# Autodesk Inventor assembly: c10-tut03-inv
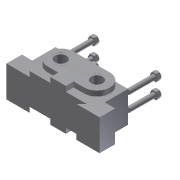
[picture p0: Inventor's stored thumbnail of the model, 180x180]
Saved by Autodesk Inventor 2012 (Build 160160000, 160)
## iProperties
Created: 2009-05
Part Number: c10-tut03-inv
Document SubType Name: Assembly
Designer: Sham
Author: Sham
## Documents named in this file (5)
- C:\Users\CadCim\Documents\SAILESH\inventor-2011-fact-prt\c10-inv-2011-prt\c10_inv_2012_prt\Tutorials\c10_tut03_inv\Double Bearing Assembly\c10-tut03-inv.iam
- C:\Users\CadCim\Documents\SAILESH\inventor-2011-fact-prt\c10-inv-2011-prt\c10_inv_2012_prt\Tutorials\c10_tut03_inv\Double Bearing Assembly\base.ipt
- C:\Users\CadCim\Documents\SAILESH\inventor-2011-fact-prt\c10-inv-2011-prt\c10_inv_2012_prt\Tutorials\c10_tut03_inv\Double Bearing Assembly\cap.ipt
- C:\Users\CadCim\Documents\SAILESH\inventor-2011-fact-prt\c10-inv-2011-prt\c10_inv_2012_prt\Tutorials\c10_tut03_inv\Double Bearing Assembly\bolt.ipt
- C:\Users\CadCim\Documents\SAILESH\inventor-2011-fact-prt\c10-inv-2011-prt\c10_inv_2012_prt\Tutorials\c10_tut03_inv\Double Bearing Assembly\bushing.ipt
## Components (10 placed, 4 different names)
1. base:1 — Mate:1, Mate:2, Mate:3, Insert:3, Insert:4
2. cap:1 — Mate:1, Mate:2, Mate:3, Insert:1, Insert:2
3. bushing:2 — Insert:3
4. bushing:3 — Insert:4
5. bolt:1 — Insert:1
6. bolt:6
7. bolt:7
8. bolt:8
9. bolt:5 — Insert:2
10. bolt:9
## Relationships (7: Insert 4, Mate 3)
- Mate:1: base:1 ↔ cap:1
- Mate:2: base:1 ↔ cap:1
- Mate:3: base:1 ↔ cap:1
- Insert:1: cap:1 ↔ bolt:1
- Insert:2: cap:1 ↔ bolt:5
- Insert:3: base:1 ↔ bushing:2
- Insert:4: base:1 ↔ bushing:3
